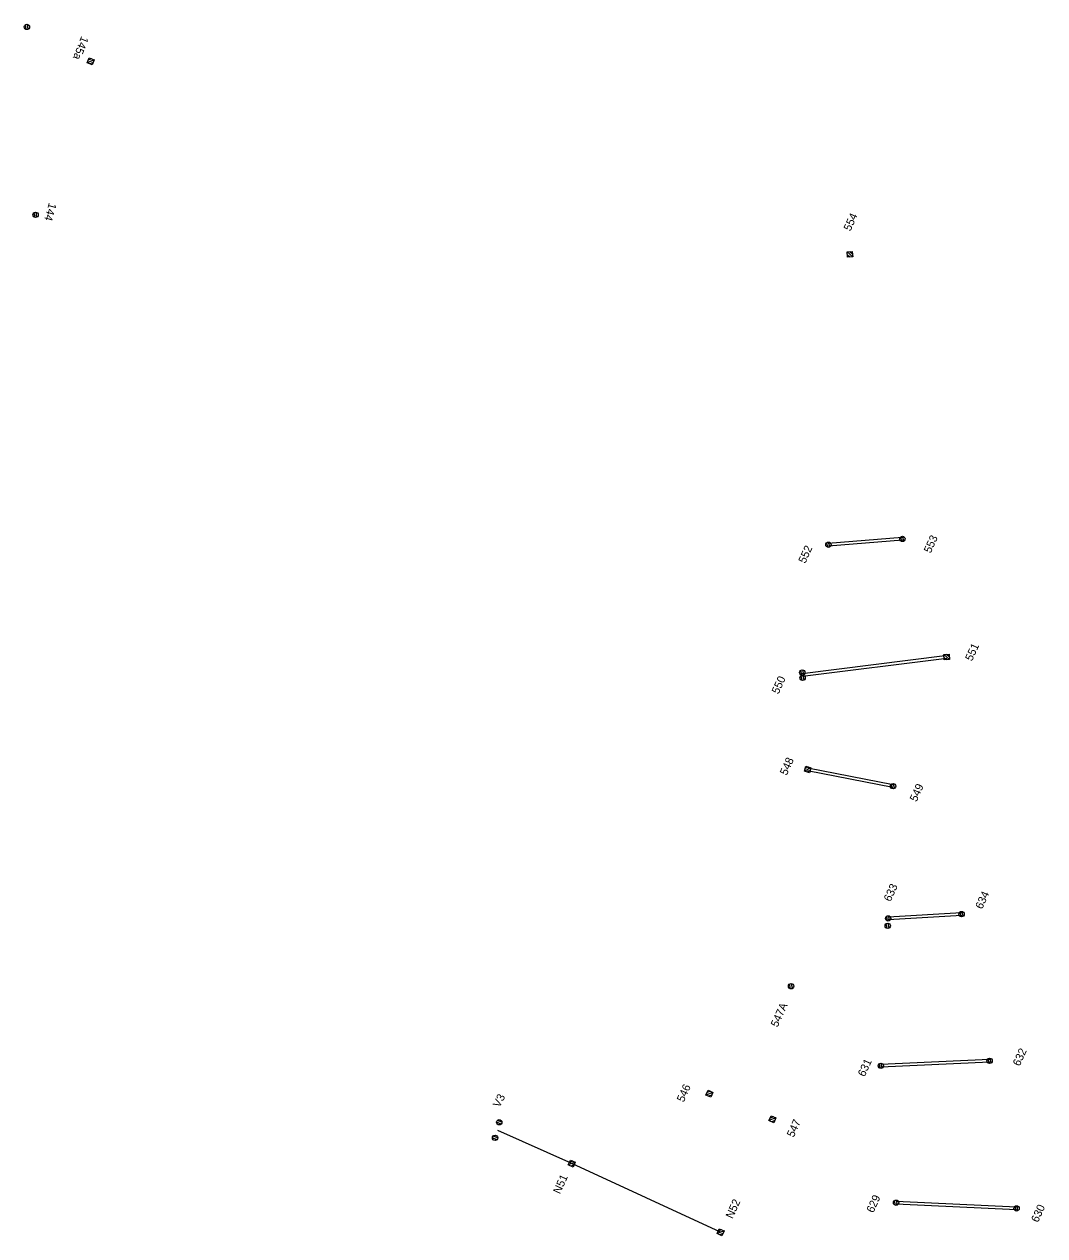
# Model space of a CAD drawing. Extents: x -595867 to -593796, y -1159595 to -1157495.
# Drawn here: x -594807.6 to -594616.4, y -1158559.5 to -1158332.5 of the extents above; entities that cross this region are included whole.
import ezdxf

# ---------------------------------------------------------------- set-up
doc = ezdxf.new("R2010")
doc.units = 0
doc.layers.add('BVK_kanalizace_jednotna_nova', color=7, linetype='Continuous')
doc.layers.add('DKM19', color=7, linetype='Continuous')

msp = doc.modelspace()

# ---------------------------------------------------------------- linework, layer by layer
at = {"layer": 'BVK_kanalizace_jednotna_nova'}
for p, q in [((-594807.2, -1158333.48), (-594807.36, -1158332.58)), ((-594806.83, -1158333.43), (-594806.99, -1158332.51)), ((-594794.5, -1158339.2), (-594795.81, -1158339.72)), ((-594794.98, -1158338.98), (-594795.6, -1158339.23)), ((-594794.71, -1158339.68), (-594795.32, -1158339.93)), ((-594805.57, -1158368.7), (-594805.73, -1158367.8)), ((-594805.2, -1158368.64), (-594805.36, -1158367.73)), ((-594652.41, -1158376.08), (-594653.47, -1158375.16)), ((-594652.94, -1158376.12), (-594653.44, -1158375.69)), ((-594652.44, -1158375.56), (-594652.95, -1158375.12)), ((-594643.21, -1158429.43), (-594643.37, -1158428.53)), ((-594642.84, -1158429.38), (-594643, -1158428.46)), ((-594657.07, -1158430.52), (-594657.23, -1158429.62)), ((-594656.7, -1158430.47), (-594656.86, -1158429.55)), ((-594634.29, -1158451.55), (-594635.35, -1158450.63)), ((-594634.82, -1158451.59), (-594635.32, -1158451.16)), ((-594634.32, -1158451.03), (-594634.83, -1158450.59)), ((-594661.96, -1158454.45), (-594662.12, -1158453.55)), ((-594661.59, -1158454.4), (-594661.76, -1158453.48)), ((-594661.53, -1158455.4), (-594661.69, -1158454.48)), ((-594661.9, -1158455.45), (-594662.06, -1158454.56)), ((-594660.23, -1158471.82), (-594661.47, -1158472.49)), ((-594660.73, -1158471.66), (-594661.32, -1158471.98)), ((-594660.38, -1158472.32), (-594660.96, -1158472.64)), ((-594644.97, -1158475.76), (-594645.13, -1158474.86)), ((-594644.6, -1158475.71), (-594644.76, -1158474.79)), ((-594645.88, -1158500.53), (-594646.04, -1158499.63)), ((-594645.51, -1158500.47), (-594645.67, -1158499.56)), ((-594632.12, -1158499.73), (-594632.28, -1158498.83)), ((-594631.75, -1158499.68), (-594631.92, -1158498.76)), ((-594645.97, -1158501.92), (-594646.13, -1158501.02)), ((-594645.6, -1158501.86), (-594645.76, -1158500.95)), ((-594664.07, -1158513.24), (-594664.23, -1158512.34)), ((-594663.7, -1158513.19), (-594663.86, -1158512.27)), ((-594626.87, -1158527.22), (-594627.03, -1158526.32)), ((-594626.5, -1158527.16), (-594626.67, -1158526.25)), ((-594647.25, -1158528.16), (-594647.41, -1158527.26)), ((-594646.88, -1158528.1), (-594647.05, -1158527.19)), ((-594678.59, -1158532.67), (-594679.91, -1158533.15)), ((-594679.06, -1158532.45), (-594679.69, -1158532.67)), ((-594678.81, -1158533.15), (-594679.43, -1158533.38)), ((-594718.26, -1158538.6), (-594719.11, -1158538.26)), ((-594718.11, -1158538.26), (-594718.97, -1158537.91)), ((-594666.79, -1158537.45), (-594668.11, -1158537.95)), ((-594667.27, -1158537.23), (-594667.89, -1158537.47)), ((-594667.01, -1158537.94), (-594667.63, -1158538.17)), ((-594719.06, -1158541.52), (-594719.91, -1158541.18)), ((-594718.91, -1158541.18), (-594719.77, -1158540.83)), ((-594704.37, -1158545.74), (-594705.69, -1158546.24)), ((-594704.85, -1158545.52), (-594705.47, -1158545.76)), ((-594704.59, -1158546.22), (-594705.2, -1158546.46)), ((-594644.4, -1158553.82), (-594644.56, -1158552.92)), ((-594644.03, -1158553.76), (-594644.19, -1158552.85)), ((-594621.82, -1158554.88), (-594621.98, -1158553.98)), ((-594621.45, -1158554.82), (-594621.61, -1158553.91)), ((-594676.5, -1158558.62), (-594677.82, -1158559.1)), ((-594676.97, -1158558.39), (-594677.6, -1158558.62)), ((-594676.72, -1158559.1), (-594677.34, -1158559.33))]:
    msp.add_line(p, q, dxfattribs=at)
for points in [[(-594794.89, -1158340.11), (-594795.81, -1158339.71), (-594795.41, -1158338.8), (-594794.5, -1158339.19)], [(-594653.4, -1158376.15), (-594653.47, -1158375.15), (-594652.48, -1158375.09), (-594652.41, -1158376.08)], [(-594635.28, -1158451.62), (-594635.35, -1158450.62), (-594634.36, -1158450.56), (-594634.29, -1158451.55)], [(-594660.51, -1158472.77), (-594661.47, -1158472.49), (-594661.19, -1158471.53), (-594660.23, -1158471.81)], [(-594679.01, -1158533.57), (-594679.91, -1158533.15), (-594679.49, -1158532.25), (-594678.59, -1158532.67)], [(-594667.2, -1158538.36), (-594668.11, -1158537.95), (-594667.7, -1158537.04), (-594666.79, -1158537.45)], [(-594704.78, -1158546.65), (-594705.69, -1158546.24), (-594705.28, -1158545.33), (-594704.37, -1158545.74)], [(-594676.92, -1158559.52), (-594677.82, -1158559.1), (-594677.4, -1158558.2), (-594676.5, -1158558.62)]]:
    msp.add_lwpolyline(points, close=True, dxfattribs=at)
for points in [[(-594794.89, -1158340.11), (-594795.81, -1158339.71), (-594795.41, -1158338.8), (-594794.5, -1158339.19), (-594794.89, -1158340.11)], [(-594653.4, -1158376.15), (-594653.47, -1158375.15), (-594652.48, -1158375.09), (-594652.41, -1158376.08), (-594653.4, -1158376.15)], [(-594643.12, -1158428.7), (-594656.98, -1158429.79)], [(-594643.08, -1158429.2), (-594656.94, -1158430.29)], [(-594635.14, -1158450.87), (-594661.85, -1158454.22)], [(-594634.79, -1158451.34), (-594661.79, -1158454.72)], [(-594635.28, -1158451.62), (-594635.35, -1158450.62), (-594634.36, -1158450.56), (-594634.29, -1158451.55), (-594635.28, -1158451.62)], [(-594660.51, -1158472.77), (-594661.47, -1158472.49), (-594661.19, -1158471.53), (-594660.23, -1158471.81), (-594660.51, -1158472.77)], [(-594644.91, -1158475.52), (-594660.9, -1158472.4)], [(-594644.82, -1158475.03), (-594660.8, -1158471.9)], [(-594632.03, -1158499), (-594645.78, -1158499.8)], [(-594632, -1158499.5), (-594645.76, -1158500.3)], [(-594626.77, -1158526.49), (-594647.15, -1158527.43)], [(-594626.75, -1158526.99), (-594647.13, -1158527.93)], [(-594679.01, -1158533.57), (-594679.91, -1158533.15), (-594679.49, -1158532.25), (-594678.59, -1158532.67), (-594679.01, -1158533.57)], [(-594667.2, -1158538.36), (-594668.11, -1158537.95), (-594667.7, -1158537.04), (-594666.79, -1158537.45), (-594667.2, -1158538.36)], [(-594705.03, -1158545.99), (-594718.9, -1158539.8)], [(-594704.78, -1158546.65), (-594705.69, -1158546.24), (-594705.28, -1158545.33), (-594704.37, -1158545.74), (-594704.78, -1158546.65)], [(-594677.16, -1158558.86), (-594705.03, -1158545.99)], [(-594621.73, -1158554.65), (-594644.3, -1158553.59)], [(-594621.7, -1158554.15), (-594644.28, -1158553.09)], [(-594676.92, -1158559.52), (-594677.82, -1158559.1), (-594677.4, -1158558.2), (-594676.5, -1158558.62), (-594676.92, -1158559.52)]]:
    msp.add_lwpolyline(points, dxfattribs=at)
for centre in [(-594807.09, -1158333), (-594807.09, -1158333), (-594805.46, -1158368.22), (-594805.46, -1158368.22), (-594643.1, -1158428.95), (-594643.1, -1158428.95), (-594656.96, -1158430.04), (-594656.96, -1158430.04), (-594661.85, -1158453.97), (-594661.85, -1158453.97), (-594661.79, -1158454.97), (-594661.79, -1158454.97), (-594644.86, -1158475.28), (-594644.86, -1158475.28), (-594645.77, -1158500.05), (-594645.77, -1158500.05), (-594632.01, -1158499.25), (-594632.01, -1158499.25), (-594645.86, -1158501.44), (-594645.86, -1158501.44), (-594663.96, -1158512.76), (-594663.96, -1158512.76), (-594626.76, -1158526.74), (-594626.76, -1158526.74), (-594647.14, -1158527.68), (-594647.14, -1158527.68), (-594718.61, -1158538.25), (-594718.61, -1158538.25), (-594719.41, -1158541.17), (-594719.41, -1158541.17), (-594644.29, -1158553.34), (-594644.29, -1158553.34), (-594621.71, -1158554.4), (-594621.71, -1158554.4)]:
    msp.add_circle(centre, 0.5, dxfattribs=at)

# ---------------------------------------------------------------- texts
for s, rotation, p in [('554', 65.5984, (-594652.84, -1158371.37)), ('553', 65.5984, (-594637.81, -1158431.72)), ('552', 65.5984, (-594661.3, -1158433.65)), ('551', 65.5984, (-594630.07, -1158451.95)), ('550', 65.5984, (-594666.31, -1158458.12)), ('548', 65.5984, (-594664.77, -1158473.36)), ('549', 65.5984, (-594640.45, -1158478.3)), ('633', 65.5984, (-594645.32, -1158497.03)), ('634', 65.5984, (-594628.17, -1158498.44)), ('547A', 65.5984, (-594666.49, -1158520.55)), ('632', 65.5984, (-594621.15, -1158527.86)), ('631', 65.5984, (-594650.17, -1158529.83)), ('546', 65.5984, (-594684.08, -1158534.6)), ('V3', 62.6209, (-594718.57, -1158535.62)), ('547', 65.5984, (-594663.47, -1158541.19)), ('N51', 65.5984, (-594707.24, -1158551.81)), ('629', 65.5984, (-594648.55, -1158555.34)), ('N52', 65.5984, (-594674.92, -1158556.44)), ('630', 65.5984, (-594617.71, -1158557.14))]:
    msp.add_text(s, height=1.5, rotation=rotation, dxfattribs=at).set_placement(p)
at = {"layer": 'DKM19'}
for s, rotation, p in [('145a', 248.6038, (-594796.87, -1158334.64)), ('144', 254.389, (-594802.95, -1158365.88))]:
    msp.add_text(s, height=1.5, rotation=rotation, dxfattribs=at).set_placement(p)

doc.saveas('drawing.dxf')
